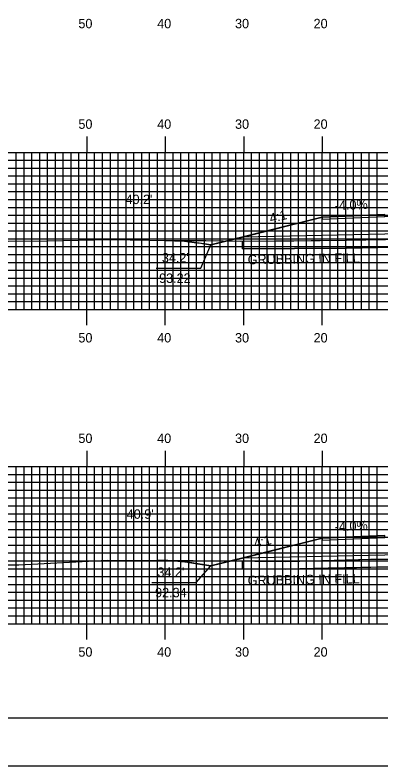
# Model space of a CAD drawing. Extents: x 1778319 to 1778662, y 442591 to 442811.
# Drawn here: x 1778425.2 to 1778471.8, y 442590.5 to 442686.2 of the extents above; entities that cross this region are included whole.
import ezdxf

# ---------------------------------------------------------------- set-up
doc = ezdxf.new("R2010")
doc.units = 0
for name, color, linetype in [('ANNOTATION', 7, 'Continuous'), ('BORDER', 7, 'Continuous'), ('D_Roadway_Centerline', 7, 'Continuous'), ('D_Roadway_Edge_Shoulder', 7, 'Continuous'), ('D_Roadway_SlopeLines', 7, 'Continuous'), ('D_Roadway_SubGrade', 7, 'Continuous'), ('D_Text_Standard', 7, 'Continuous'), ('GRUBBING IN FILL', 7, 'Continuous'), ('H_V ANNOTATION', 7, 'Continuous'), ('MAJOR', 7, 'Continuous'), ('MINOR', 7, 'Continuous'), ('PLOT BOUNDARY', 7, 'Continuous'), ('S_Roadway_Centerline', 7, 'Continuous')]:
    doc.layers.add(name, color=color, linetype=linetype)

msp = doc.modelspace()

# ---------------------------------------------------------------- linework, layer by layer
at = {"layer": 'ANNOTATION'}
for points in [[(1778443.139, 442653.921), (1778448.831, 442653.921), (1778450.129, 442656.884)], [(1778442.572, 442613.898), (1778448.264, 442613.898), (1778450.129, 442616.009)]]:
    msp.add_lwpolyline(points, dxfattribs=at)
at = {"layer": 'BORDER'}
msp.add_lwpolyline([(1778334.703, 442596.665), (1778654.703, 442596.665), (1778654.703, 442806.665), (1778334.703, 442806.665)], close=True, dxfattribs=at)
at = {"layer": 'D_Roadway_Centerline'}
for points in [[(1778444.249, 442657.449), (1778444.667, 442657.44), (1778445.5, 442657.422), (1778446.735, 442657.345), (1778446.75, 442657.344), (1778447.999, 442657.213), (1778448.852, 442657.089), (1778449.25, 442657.031), (1778450.129, 442656.884), (1778454.129, 442657.884), (1778460.479, 442659.471), (1778464.303, 442660.427), (1778472.303, 442660.747)], [(1778443.396, 442616.723), (1778444.552, 442616.695), (1778444.645, 442616.693), (1778445.895, 442616.612), (1778446.8, 442616.517), (1778447.146, 442616.481), (1778447.658, 442616.406), (1778448.395, 442616.298), (1778450.129, 442616.009), (1778454.129, 442617.009), (1778464.303, 442619.552), (1778472.304, 442619.872)]]:
    msp.add_lwpolyline(points, dxfattribs=at)
at = {"layer": 'D_Roadway_Edge_Shoulder'}
for points in [[(1778472.303, 442660.747), (1778464.303, 442660.427), (1778464.303, 442660.177), (1778472.303, 442660.497)], [(1778472.304, 442619.872), (1778464.303, 442619.552), (1778464.303, 442619.302), (1778472.304, 442619.622)]]:
    msp.add_lwpolyline(points, close=True, dxfattribs=at)
at = {"layer": 'D_Roadway_SlopeLines'}
for points in [[(1778464.303, 442660.427), (1778450.129, 442656.884)], [(1778450.129, 442656.884), (1778449.25, 442657.031), (1778447.999, 442657.213), (1778446.75, 442657.344), (1778445.5, 442657.422), (1778444.249, 442657.449)], [(1778464.303, 442619.552), (1778450.129, 442616.009)], [(1778450.129, 442616.009), (1778448.395, 442616.298), (1778447.146, 442616.481), (1778445.895, 442616.612), (1778444.645, 442616.693), (1778443.396, 442616.723)], [(1778450.129, 442616.009), (1778447.146, 442616.481), (1778445.895, 442616.612), (1778444.645, 442616.693), (1778443.396, 442616.723)]]:
    msp.add_lwpolyline(points, dxfattribs=at)
at = {"layer": 'D_Roadway_SubGrade'}
for points in [[(1778472.303, 442658.247), (1778454.129, 442657.884), (1778464.303, 442660.427), (1778464.303, 442660.177), (1778472.303, 442660.497), (1778484.303, 442660.737), (1778496.303, 442660.497), (1778504.303, 442660.177), (1778504.303, 442660.427), (1778514.477, 442657.884), (1778496.303, 442658.247), (1778484.303, 442658.487)], [(1778472.304, 442617.372), (1778454.129, 442617.009), (1778464.303, 442619.552), (1778464.303, 442619.302), (1778472.304, 442619.622), (1778484.303, 442619.862), (1778496.303, 442619.622), (1778504.303, 442619.302), (1778504.303, 442619.552), (1778514.476, 442617.009), (1778496.303, 442617.372), (1778484.303, 442617.612)]]:
    msp.add_lwpolyline(points, close=True, dxfattribs=at)
at = {"layer": 'GRUBBING IN FILL'}
msp.add_line((1778454.129, 442657.366), (1778454.129, 442656.366), dxfattribs=at)
msp.add_line((1778454.129, 442657.366), (1778454.129, 442656.366), dxfattribs=at)
for points in [[(1778454.129, 442657.366), (1778460.678, 442657.418), (1778467.406, 442657.472), (1778472.384, 442657.577), (1778477.362, 442657.682), (1778484.006, 442657.949), (1778484.303, 442657.961), (1778484.303, 442656.961), (1778484.032, 442656.95), (1778477.393, 442656.683), (1778472.407, 442656.577), (1778467.421, 442656.472), (1778460.775, 442656.419), (1778454.129, 442656.366)], [(1778454.129, 442657.366), (1778460.678, 442657.418), (1778467.406, 442657.472), (1778472.384, 442657.577), (1778477.362, 442657.682), (1778484.006, 442657.949), (1778484.303, 442657.961), (1778484.303, 442656.961), (1778484.032, 442656.95), (1778477.393, 442656.683), (1778472.407, 442656.577), (1778467.421, 442656.472), (1778460.775, 442656.419), (1778454.129, 442656.366)], [(1778454.129, 442615.647), (1778454.129, 442616.647), (1778459.638, 442616.593), (1778465.061, 442616.725), (1778470.483, 442616.858), (1778472.182, 442616.893), (1778473.6, 442616.865), (1778482.935, 442616.806), (1778484.303, 442616.797), (1778484.303, 442615.797), (1778482.931, 442615.806), (1778473.587, 442615.865), (1778471.344, 442615.876), (1778465.076, 442615.725), (1778459.645, 442615.592), (1778456.887, 442615.62)], [(1778454.129, 442615.647), (1778454.129, 442616.647), (1778459.638, 442616.593), (1778465.061, 442616.725), (1778470.483, 442616.858), (1778472.182, 442616.893), (1778473.6, 442616.865), (1778482.935, 442616.806), (1778484.303, 442616.797), (1778484.303, 442615.797), (1778482.931, 442615.806), (1778473.587, 442615.865), (1778471.344, 442615.876), (1778465.076, 442615.725), (1778459.645, 442615.592), (1778456.887, 442615.62)]]:
    msp.add_lwpolyline(points, close=True, dxfattribs=at)
for points in [[(1778454.129, 442656.366), (1778467.421, 442656.472), (1778477.393, 442656.683), (1778490.671, 442657.217), (1778501.299, 442657.221), (1778507.247, 442656.926), (1778512.45, 442656.908), (1778514.477, 442656.914)], [(1778454.129, 442656.366), (1778467.421, 442656.472), (1778477.393, 442656.683), (1778490.671, 442657.217), (1778501.299, 442657.221), (1778507.247, 442656.926), (1778512.45, 442656.908), (1778514.477, 442656.914)], [(1778454.129, 442615.647), (1778459.645, 442615.592), (1778470.506, 442615.858), (1778472.182, 442615.893), (1778473.587, 442615.865), (1778492.274, 442615.747), (1778493.957, 442615.775), (1778495.773, 442615.754), (1778505.903, 442615.749), (1778514.476, 442615.871)], [(1778454.129, 442615.647), (1778459.645, 442615.592), (1778470.506, 442615.858), (1778472.182, 442615.893), (1778473.587, 442615.865), (1778492.274, 442615.747), (1778493.957, 442615.775), (1778495.773, 442615.754), (1778505.903, 442615.749), (1778514.476, 442615.871)]]:
    msp.add_lwpolyline(points, dxfattribs=at)
at = {"layer": 'MAJOR'}
for p, q in [((1778434.303, 442670.669), (1778434.303, 442668.665)), ((1778444.303, 442670.669), (1778444.303, 442668.665)), ((1778454.303, 442670.669), (1778454.303, 442668.665)), ((1778464.303, 442670.669), (1778464.303, 442668.665)), ((1778344.303, 442668.665), (1778624.303, 442668.665)), ((1778344.303, 442668.665), (1778624.303, 442668.665)), ((1778434.303, 442648.665), (1778434.303, 442668.665)), ((1778444.303, 442648.665), (1778444.303, 442668.665)), ((1778454.303, 442648.665), (1778454.303, 442668.665)), ((1778464.303, 442648.665), (1778464.303, 442668.665)), ((1778344.303, 442663.665), (1778624.303, 442663.665)), ((1778344.303, 442658.665), (1778624.303, 442658.665)), ((1778344.303, 442653.665), (1778624.303, 442653.665)), ((1778344.303, 442648.665), (1778624.303, 442648.665)), ((1778344.303, 442648.665), (1778624.303, 442648.665)), ((1778434.303, 442646.661), (1778434.303, 442648.665)), ((1778444.303, 442646.661), (1778444.303, 442648.665)), ((1778454.303, 442646.661), (1778454.303, 442648.665)), ((1778464.303, 442646.661), (1778464.303, 442648.665)), ((1778434.303, 442630.669), (1778434.303, 442628.665)), ((1778444.303, 442630.669), (1778444.303, 442628.665)), ((1778454.303, 442630.669), (1778454.303, 442628.665)), ((1778464.303, 442630.669), (1778464.303, 442628.665)), ((1778344.303, 442628.665), (1778624.303, 442628.665)), ((1778344.303, 442628.665), (1778624.303, 442628.665)), ((1778434.303, 442608.665), (1778434.303, 442628.665)), ((1778444.303, 442608.665), (1778444.303, 442628.665)), ((1778454.303, 442608.665), (1778454.303, 442628.665)), ((1778464.303, 442608.665), (1778464.303, 442628.665)), ((1778344.303, 442623.665), (1778624.303, 442623.665)), ((1778344.303, 442618.665), (1778624.303, 442618.665)), ((1778344.303, 442613.665), (1778624.303, 442613.665)), ((1778344.303, 442608.665), (1778624.303, 442608.665)), ((1778344.303, 442608.665), (1778624.303, 442608.665)), ((1778434.303, 442606.661), (1778434.303, 442608.665)), ((1778444.303, 442606.661), (1778444.303, 442608.665)), ((1778454.303, 442606.661), (1778454.303, 442608.665)), ((1778464.303, 442606.661), (1778464.303, 442608.665))]:
    msp.add_line(p, q, dxfattribs=at)
at = {"layer": 'MINOR'}
for p, q in [((1778425.303, 442648.665), (1778425.303, 442668.665)), ((1778426.303, 442648.665), (1778426.303, 442668.665)), ((1778427.303, 442648.665), (1778427.303, 442668.665)), ((1778428.303, 442648.665), (1778428.303, 442668.665)), ((1778429.303, 442648.665), (1778429.303, 442668.665)), ((1778430.303, 442648.665), (1778430.303, 442668.665)), ((1778431.303, 442648.665), (1778431.303, 442668.665)), ((1778432.303, 442648.665), (1778432.303, 442668.665)), ((1778433.303, 442648.665), (1778433.303, 442668.665)), ((1778435.303, 442648.665), (1778435.303, 442668.665)), ((1778436.303, 442648.665), (1778436.303, 442668.665)), ((1778437.303, 442648.665), (1778437.303, 442668.665)), ((1778438.303, 442648.665), (1778438.303, 442668.665)), ((1778439.303, 442648.665), (1778439.303, 442668.665)), ((1778440.303, 442648.665), (1778440.303, 442668.665)), ((1778441.303, 442648.665), (1778441.303, 442668.665)), ((1778442.303, 442648.665), (1778442.303, 442668.665)), ((1778443.303, 442648.665), (1778443.303, 442668.665)), ((1778445.303, 442648.665), (1778445.303, 442668.665)), ((1778446.303, 442648.665), (1778446.303, 442668.665)), ((1778447.303, 442648.665), (1778447.303, 442668.665)), ((1778448.303, 442648.665), (1778448.303, 442668.665)), ((1778449.303, 442648.665), (1778449.303, 442668.665)), ((1778450.303, 442648.665), (1778450.303, 442668.665)), ((1778451.303, 442648.665), (1778451.303, 442668.665)), ((1778452.303, 442648.665), (1778452.303, 442668.665)), ((1778453.303, 442648.665), (1778453.303, 442668.665)), ((1778455.303, 442648.665), (1778455.303, 442668.665)), ((1778456.303, 442648.665), (1778456.303, 442668.665)), ((1778457.303, 442648.665), (1778457.303, 442668.665)), ((1778458.303, 442648.665), (1778458.303, 442668.665)), ((1778459.303, 442648.665), (1778459.303, 442668.665)), ((1778460.303, 442648.665), (1778460.303, 442668.665)), ((1778461.303, 442648.665), (1778461.303, 442668.665)), ((1778462.303, 442648.665), (1778462.303, 442668.665)), ((1778463.303, 442648.665), (1778463.303, 442668.665)), ((1778465.303, 442648.665), (1778465.303, 442668.665)), ((1778466.303, 442648.665), (1778466.303, 442668.665)), ((1778467.303, 442648.665), (1778467.303, 442668.665)), ((1778468.303, 442648.665), (1778468.303, 442668.665)), ((1778469.303, 442648.665), (1778469.303, 442668.665)), ((1778470.303, 442648.665), (1778470.303, 442668.665)), ((1778471.303, 442648.665), (1778471.303, 442668.665)), ((1778344.303, 442667.665), (1778624.303, 442667.665)), ((1778344.303, 442666.665), (1778624.303, 442666.665)), ((1778344.303, 442665.665), (1778624.303, 442665.665)), ((1778344.303, 442664.665), (1778624.303, 442664.665)), ((1778344.303, 442662.665), (1778624.303, 442662.665)), ((1778344.303, 442661.665), (1778624.303, 442661.665)), ((1778344.303, 442660.665), (1778624.303, 442660.665)), ((1778344.303, 442659.665), (1778624.303, 442659.665)), ((1778344.303, 442657.665), (1778624.303, 442657.665)), ((1778344.303, 442656.665), (1778624.303, 442656.665)), ((1778344.303, 442655.665), (1778624.303, 442655.665)), ((1778344.303, 442654.665), (1778624.303, 442654.665)), ((1778344.303, 442652.665), (1778624.303, 442652.665)), ((1778344.303, 442651.665), (1778624.303, 442651.665)), ((1778344.303, 442650.665), (1778624.303, 442650.665)), ((1778344.303, 442649.665), (1778624.303, 442649.665)), ((1778425.303, 442608.665), (1778425.303, 442628.665)), ((1778426.303, 442608.665), (1778426.303, 442628.665)), ((1778427.303, 442608.665), (1778427.303, 442628.665)), ((1778428.303, 442608.665), (1778428.303, 442628.665)), ((1778429.303, 442608.665), (1778429.303, 442628.665)), ((1778430.303, 442608.665), (1778430.303, 442628.665)), ((1778431.303, 442608.665), (1778431.303, 442628.665)), ((1778432.303, 442608.665), (1778432.303, 442628.665)), ((1778433.303, 442608.665), (1778433.303, 442628.665)), ((1778435.303, 442608.665), (1778435.303, 442628.665)), ((1778436.303, 442608.665), (1778436.303, 442628.665)), ((1778437.303, 442608.665), (1778437.303, 442628.665)), ((1778438.303, 442608.665), (1778438.303, 442628.665)), ((1778439.303, 442608.665), (1778439.303, 442628.665)), ((1778440.303, 442608.665), (1778440.303, 442628.665)), ((1778441.303, 442608.665), (1778441.303, 442628.665)), ((1778442.303, 442608.665), (1778442.303, 442628.665)), ((1778443.303, 442608.665), (1778443.303, 442628.665)), ((1778445.303, 442608.665), (1778445.303, 442628.665)), ((1778446.303, 442608.665), (1778446.303, 442628.665)), ((1778447.303, 442608.665), (1778447.303, 442628.665)), ((1778448.303, 442608.665), (1778448.303, 442628.665)), ((1778449.303, 442608.665), (1778449.303, 442628.665)), ((1778450.303, 442608.665), (1778450.303, 442628.665)), ((1778451.303, 442608.665), (1778451.303, 442628.665)), ((1778452.303, 442608.665), (1778452.303, 442628.665)), ((1778453.303, 442608.665), (1778453.303, 442628.665)), ((1778455.303, 442608.665), (1778455.303, 442628.665)), ((1778456.303, 442608.665), (1778456.303, 442628.665)), ((1778457.303, 442608.665), (1778457.303, 442628.665)), ((1778458.303, 442608.665), (1778458.303, 442628.665)), ((1778459.303, 442608.665), (1778459.303, 442628.665)), ((1778460.303, 442608.665), (1778460.303, 442628.665)), ((1778461.303, 442608.665), (1778461.303, 442628.665)), ((1778462.303, 442608.665), (1778462.303, 442628.665)), ((1778463.303, 442608.665), (1778463.303, 442628.665)), ((1778465.303, 442608.665), (1778465.303, 442628.665)), ((1778466.303, 442608.665), (1778466.303, 442628.665)), ((1778467.303, 442608.665), (1778467.303, 442628.665)), ((1778468.303, 442608.665), (1778468.303, 442628.665)), ((1778469.303, 442608.665), (1778469.303, 442628.665)), ((1778470.303, 442608.665), (1778470.303, 442628.665)), ((1778471.303, 442608.665), (1778471.303, 442628.665)), ((1778344.303, 442627.665), (1778624.303, 442627.665)), ((1778344.303, 442626.665), (1778624.303, 442626.665)), ((1778344.303, 442625.665), (1778624.303, 442625.665)), ((1778344.303, 442624.665), (1778624.303, 442624.665)), ((1778344.303, 442622.665), (1778624.303, 442622.665)), ((1778344.303, 442621.665), (1778624.303, 442621.665)), ((1778344.303, 442620.665), (1778624.303, 442620.665)), ((1778344.303, 442619.665), (1778624.303, 442619.665)), ((1778344.303, 442617.665), (1778624.303, 442617.665)), ((1778344.303, 442616.665), (1778624.303, 442616.665)), ((1778344.303, 442615.665), (1778624.303, 442615.665)), ((1778344.303, 442614.665), (1778624.303, 442614.665)), ((1778344.303, 442612.665), (1778624.303, 442612.665)), ((1778344.303, 442611.665), (1778624.303, 442611.665)), ((1778344.303, 442610.665), (1778624.303, 442610.665)), ((1778344.303, 442609.665), (1778624.303, 442609.665))]:
    msp.add_line(p, q, dxfattribs=at)
at = {"layer": 'PLOT BOUNDARY'}
msp.add_lwpolyline([(1778318.516, 442590.547), (1778658.516, 442590.547), (1778658.516, 442810.547), (1778318.516, 442810.547)], close=True, dxfattribs=at)
at = {"layer": 'S_Roadway_Centerline'}
for points in [[(1778344.303, 442656.471), (1778344.405, 442656.479), (1778353.961, 442656.277), (1778358.625, 442656.431), (1778376.722, 442656.73), (1778379.183, 442656.575), (1778398.717, 442657.351), (1778401.625, 442657.468), (1778421.743, 442657.422), (1778424.302, 442657.366), (1778429.2, 442657.402), (1778437.29, 442657.57), (1778444.876, 442657.439), (1778449.457, 442657.46), (1778453.95, 442657.364), (1778467.406, 442657.472), (1778477.362, 442657.682), (1778490.651, 442658.217), (1778501.324, 442658.221), (1778507.274, 442657.926), (1778512.45, 442657.908), (1778518.537, 442657.927), (1778524.414, 442658.023), (1778539.78, 442658.085)], [(1778402.176, 442616.154), (1778425.622, 442616.168), (1778426.457, 442616.2), (1778436.939, 442616.743), (1778447.845, 442616.709), (1778459.638, 442616.593), (1778470.483, 442616.858), (1778472.182, 442616.893), (1778473.6, 442616.865), (1778492.269, 442616.747), (1778493.954, 442616.775), (1778495.779, 442616.754), (1778505.896, 442616.749), (1778519.459, 442616.942), (1778526.587, 442616.872), (1778539.023, 442616.524)]]:
    msp.add_lwpolyline(points, dxfattribs=at)

# ---------------------------------------------------------------- texts
at = {"layer": 'ANNOTATION'}
for s, rotation, p in [('-4.0%', 2.29053, (1778465.935, 442661.294)), ('4:1', 14.03386, (1778457.751, 442659.651)), ('-4.0%', 2.29053, (1778465.935, 442620.419)), ('4:1', 14.03404, (1778455.752, 442618.276))]:
    msp.add_text(s, height=1.2, rotation=rotation, dxfattribs=at).set_placement(p)
for s, p in [("34.2'", (1778443.874, 442654.648)), ('93.22', (1778443.521, 442652.048)), ("34.2'", (1778443.307, 442614.624)), ('92.34', (1778443.012, 442612.024))]:
    msp.add_text(s, height=1.2, dxfattribs=at).set_placement(p)
at = {"layer": 'D_Text_Standard'}
for s, p in [("40.2'", (1778439.243, 442662.082)), ("40.9'", (1778439.394, 442622.019))]:
    msp.add_text(s, height=1.2, dxfattribs=at).set_placement(p)
at = {"layer": 'GRUBBING IN FILL'}
for p in [(1778454.821, 442654.409), (1778454.821, 442613.562)]:
    msp.add_text('GRUBBING IN FILL', height=1.2, rotation=0.93789, dxfattribs=at).set_placement(p)
at = {"layer": 'H_V ANNOTATION'}
for s, p in [('50', (1778433.232, 442684.465)), ('40', (1778443.275, 442684.465)), ('30', (1778453.2, 442684.465)), ('20', (1778463.211, 442684.465)), ('50', (1778433.232, 442671.665)), ('40', (1778443.275, 442671.665)), ('30', (1778453.2, 442671.665)), ('20', (1778463.211, 442671.665)), ('50', (1778433.232, 442644.465)), ('40', (1778443.275, 442644.465)), ('30', (1778453.2, 442644.465)), ('20', (1778463.211, 442644.465)), ('50', (1778433.232, 442631.665)), ('40', (1778443.275, 442631.665)), ('30', (1778453.2, 442631.665)), ('20', (1778463.211, 442631.665)), ('50', (1778433.232, 442604.465)), ('40', (1778443.275, 442604.465)), ('30', (1778453.2, 442604.465)), ('20', (1778463.211, 442604.465))]:
    msp.add_text(s, height=1.2, dxfattribs=at).set_placement(p)

doc.saveas('drawing.dxf')
